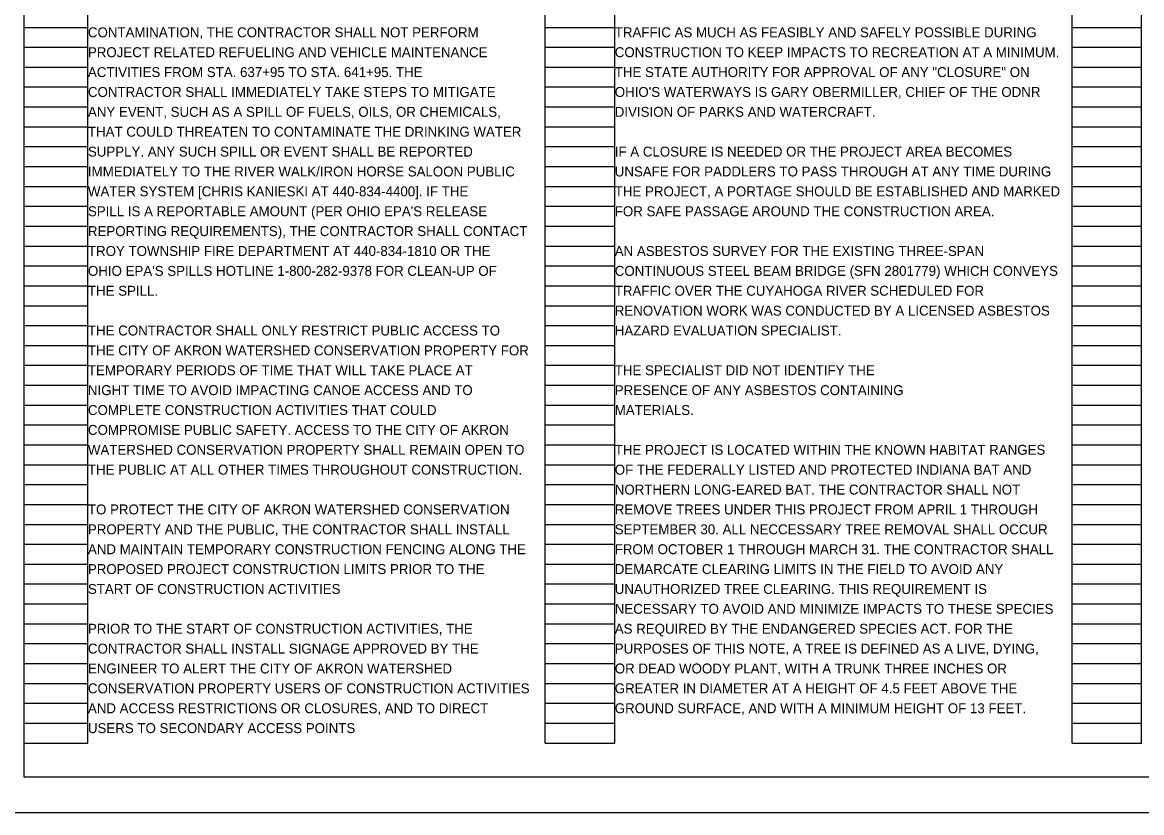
# Model space of a CAD drawing. Extents: x -6.4 to 41.8, y 0 to 22.
# Drawn here: x 1.98 to 17.74, y 0 to 11.13 of the extents above; entities that cross this region are included whole.
import ezdxf

# ---------------------------------------------------------------- set-up
doc = ezdxf.new("R2010")
doc.units = 0
for name, color, linetype in [('SC_Scratch1', 7, 'Continuous'), ('SH_Border', 7, 'Continuous'), ('SH_Cut_Line', 7, 'Continuous'), ('SH_Text', 7, 'Continuous')]:
    doc.layers.add(name, color=color, linetype=linetype)

msp = doc.modelspace()

# ---------------------------------------------------------------- linework, layer by layer
at = {"layer": 'SC_Scratch1'}
for p, q in [((2, 0.98), (2, 21.14)), ((2.9, 0.98), (2.9, 21.14)), ((9.34, 0.98), (9.34, 21.14)), ((10.32, 0.98), (10.32, 21.14)), ((16.76, 0.98), (16.76, 21.14)), ((17.74, 0.98), (17.74, 21.14)), ((2, 11.06), (2.9, 11.06)), ((9.34, 11.06), (10.32, 11.06)), ((16.76, 11.06), (17.74, 11.06)), ((2, 10.78), (2.9, 10.78)), ((9.34, 10.78), (10.32, 10.78)), ((16.76, 10.78), (17.74, 10.78)), ((2, 10.5), (2.9, 10.5)), ((9.34, 10.5), (10.32, 10.5)), ((16.76, 10.5), (17.74, 10.5)), ((2, 10.22), (2.9, 10.22)), ((9.34, 10.22), (10.32, 10.22)), ((16.76, 10.22), (17.74, 10.22)), ((2, 9.94), (2.9, 9.94)), ((9.34, 9.94), (10.32, 9.94)), ((16.76, 9.94), (17.74, 9.94)), ((2, 9.66), (2.9, 9.66)), ((9.34, 9.66), (10.32, 9.66)), ((16.76, 9.66), (17.74, 9.66)), ((2, 9.38), (2.9, 9.38)), ((9.34, 9.38), (10.32, 9.38)), ((16.76, 9.38), (17.74, 9.38)), ((2, 9.1), (2.9, 9.1)), ((9.34, 9.1), (10.32, 9.1)), ((16.76, 9.1), (17.74, 9.1)), ((2, 8.82), (2.9, 8.82)), ((9.34, 8.82), (10.32, 8.82)), ((16.76, 8.82), (17.74, 8.82)), ((2, 8.54), (2.9, 8.54)), ((9.34, 8.54), (10.32, 8.54)), ((16.76, 8.54), (17.74, 8.54)), ((2, 8.26), (2.9, 8.26)), ((9.34, 8.26), (10.32, 8.26)), ((16.76, 8.26), (17.74, 8.26)), ((2, 7.98), (2.9, 7.98)), ((9.34, 7.98), (10.32, 7.98)), ((16.76, 7.98), (17.74, 7.98)), ((2, 7.7), (2.9, 7.7)), ((9.34, 7.7), (10.32, 7.7)), ((16.76, 7.7), (17.74, 7.7)), ((2, 7.42), (2.9, 7.42)), ((9.34, 7.42), (10.32, 7.42)), ((16.76, 7.42), (17.74, 7.42)), ((2, 7.14), (2.9, 7.14)), ((9.34, 7.14), (10.32, 7.14)), ((16.76, 7.14), (17.74, 7.14)), ((2, 6.86), (2.9, 6.86)), ((9.34, 6.86), (10.32, 6.86)), ((16.76, 6.86), (17.74, 6.86)), ((2, 6.58), (2.9, 6.58)), ((9.34, 6.58), (10.32, 6.58)), ((16.76, 6.58), (17.74, 6.58)), ((2, 6.3), (2.9, 6.3)), ((9.34, 6.3), (10.32, 6.3)), ((16.76, 6.3), (17.74, 6.3)), ((2, 6.02), (2.9, 6.02)), ((9.34, 6.02), (10.32, 6.02)), ((16.76, 6.02), (17.74, 6.02)), ((2, 5.74), (2.9, 5.74)), ((9.34, 5.74), (10.32, 5.74)), ((16.76, 5.74), (17.74, 5.74)), ((2, 5.46), (2.9, 5.46)), ((9.34, 5.46), (10.32, 5.46)), ((16.76, 5.46), (17.74, 5.46)), ((2, 5.18), (2.9, 5.18)), ((9.34, 5.18), (10.32, 5.18)), ((16.76, 5.18), (17.74, 5.18)), ((2, 4.9), (2.9, 4.9)), ((9.34, 4.9), (10.32, 4.9)), ((16.76, 4.9), (17.74, 4.9)), ((2, 4.62), (2.9, 4.62)), ((9.34, 4.62), (10.32, 4.62)), ((16.76, 4.62), (17.74, 4.62)), ((2, 4.34), (2.9, 4.34)), ((9.34, 4.34), (10.32, 4.34)), ((16.76, 4.34), (17.74, 4.34)), ((2, 4.06), (2.9, 4.06)), ((9.34, 4.06), (10.32, 4.06)), ((16.76, 4.06), (17.74, 4.06)), ((2, 3.78), (2.9, 3.78)), ((9.34, 3.78), (10.32, 3.78)), ((16.76, 3.78), (17.74, 3.78)), ((2, 3.5), (2.9, 3.5)), ((9.34, 3.5), (10.32, 3.5)), ((16.76, 3.5), (17.74, 3.5)), ((2, 3.22), (2.9, 3.22)), ((9.34, 3.22), (10.32, 3.22)), ((16.76, 3.22), (17.74, 3.22)), ((2, 2.94), (2.9, 2.94)), ((9.34, 2.94), (10.32, 2.94)), ((16.76, 2.94), (17.74, 2.94)), ((2, 2.66), (2.9, 2.66)), ((9.34, 2.66), (10.32, 2.66)), ((16.76, 2.66), (17.74, 2.66)), ((2, 2.38), (2.9, 2.38)), ((9.34, 2.38), (10.32, 2.38)), ((16.76, 2.38), (17.74, 2.38)), ((2, 2.1), (2.9, 2.1)), ((9.34, 2.1), (10.32, 2.1)), ((16.76, 2.1), (17.74, 2.1)), ((2, 1.82), (2.9, 1.82)), ((9.34, 1.82), (10.32, 1.82)), ((16.76, 1.82), (17.74, 1.82)), ((2, 1.54), (2.9, 1.54)), ((9.34, 1.54), (10.32, 1.54)), ((16.76, 1.54), (17.74, 1.54)), ((2, 1.26), (2.9, 1.26)), ((9.34, 1.26), (10.32, 1.26)), ((16.76, 1.26), (17.74, 1.26)), ((2, 0.98), (2.9, 0.98)), ((9.34, 0.98), (10.32, 0.98)), ((16.76, 0.98), (17.74, 0.98))]:
    msp.add_line(p, q, dxfattribs=at)
at = {"layer": 'SH_Border'}
msp.add_lwpolyline([(2, 21.5), (33.5, 21.5), (33.5, 0.5), (2, 0.5)], close=True, dxfattribs=at)
at = {"layer": 'SH_Cut_Line'}
msp.add_lwpolyline([(0, 0), (34, 0), (34, 22), (0, 22)], close=True, dxfattribs=at)

# ---------------------------------------------------------------- texts
at = {"layer": 'SH_Text'}
for s, p in [('CONTAMINATION, THE CONTRACTOR SHALL NOT PERFORM ', (2.9, 10.92)), ('TRAFFIC AS MUCH AS FEASIBLY AND SAFELY POSSIBLE DURING ', (10.32, 10.92)), ('PROJECT RELATED REFUELING AND VEHICLE MAINTENANCE ', (2.9, 10.64)), ('CONSTRUCTION TO KEEP IMPACTS TO RECREATION AT A MINIMUM. ', (10.32, 10.64)), ('ACTIVITIES FROM STA. 637+95 TO STA. 641+95. THE ', (2.9, 10.36)), ('THE STATE AUTHORITY FOR APPROVAL OF ANY "CLOSURE" ON ', (10.32, 10.36)), ('CONTRACTOR SHALL IMMEDIATELY TAKE STEPS TO MITIGATE ', (2.9, 10.08)), ("OHIO'S WATERWAYS IS GARY OBERMILLER, CHIEF OF THE ODNR ", (10.32, 10.08)), ('ANY EVENT, SUCH AS A SPILL OF FUELS, OILS, OR CHEMICALS, ', (2.9, 9.8)), ('DIVISION OF PARKS AND WATERCRAFT. ', (10.32, 9.8)), ('THAT COULD THREATEN TO CONTAMINATE THE DRINKING WATER ', (2.9, 9.52)), ('SUPPLY. ANY SUCH SPILL OR EVENT SHALL BE REPORTED ', (2.9, 9.24)), ('IF A CLOSURE IS NEEDED OR THE PROJECT AREA BECOMES ', (10.32, 9.24)), ('IMMEDIATELY TO THE RIVER WALK/IRON HORSE SALOON PUBLIC ', (2.9, 8.96)), ('UNSAFE FOR PADDLERS TO PASS THROUGH AT ANY TIME DURING ', (10.32, 8.96)), ('WATER SYSTEM [CHRIS KANIESKI AT 440-834-4400]. IF THE ', (2.9, 8.68)), ('THE PROJECT, A PORTAGE SHOULD BE ESTABLISHED AND MARKED ', (10.32, 8.68)), ("SPILL IS A REPORTABLE AMOUNT (PER OHIO EPA'S RELEASE ", (2.9, 8.4)), ('FOR SAFE PASSAGE AROUND THE CONSTRUCTION AREA. ', (10.32, 8.4)), ('REPORTING REQUIREMENTS), THE CONTRACTOR SHALL CONTACT ', (2.9, 8.12)), ('TROY TOWNSHIP FIRE DEPARTMENT AT 440-834-1810 OR THE ', (2.9, 7.84)), ('AN ASBESTOS SURVEY FOR THE EXISTING THREE-SPAN ', (10.32, 7.84)), ("OHIO EPA'S SPILLS HOTLINE 1-800-282-9378 FOR CLEAN-UP OF ", (2.9, 7.56)), ('CONTINUOUS STEEL BEAM BRIDGE (SFN 2801779) WHICH CONVEYS ', (10.32, 7.56)), ('THE SPILL. ', (2.9, 7.28)), ('TRAFFIC OVER THE CUYAHOGA RIVER SCHEDULED FOR ', (10.32, 7.28)), ('RENOVATION WORK WAS CONDUCTED BY A LICENSED ASBESTOS ', (10.32, 7)), ('THE CONTRACTOR SHALL ONLY RESTRICT PUBLIC ACCESS TO ', (2.9, 6.72)), ('HAZARD EVALUATION SPECIALIST.', (10.32, 6.72)), ('THE CITY OF AKRON WATERSHED CONSERVATION PROPERTY FOR ', (2.9, 6.44)), ('TEMPORARY PERIODS OF TIME THAT WILL TAKE PLACE AT ', (2.9, 6.16)), ('THE SPECIALIST DID NOT IDENTIFY THE ', (10.32, 6.16)), ('NIGHT TIME TO AVOID IMPACTING CANOE ACCESS AND TO ', (2.9, 5.88)), ('PRESENCE OF ANY ASBESTOS CONTAINING', (10.32, 5.88)), ('COMPLETE CONSTRUCTION ACTIVITIES THAT COULD ', (2.9, 5.6)), ('MATERIALS.', (10.32, 5.6)), ('COMPROMISE PUBLIC SAFETY. ACCESS TO THE CITY OF AKRON ', (2.9, 5.32)), ('WATERSHED CONSERVATION PROPERTY SHALL REMAIN OPEN TO ', (2.9, 5.04)), ('THE PROJECT IS LOCATED WITHIN THE KNOWN HABITAT RANGES ', (10.32, 5.04)), ('THE PUBLIC AT ALL OTHER TIMES THROUGHOUT CONSTRUCTION. ', (2.9, 4.76)), ('OF THE FEDERALLY LISTED AND PROTECTED INDIANA BAT AND ', (10.32, 4.76)), ('NORTHERN LONG-EARED BAT. THE CONTRACTOR SHALL NOT ', (10.32, 4.48)), ('TO PROTECT THE CITY OF AKRON WATERSHED CONSERVATION ', (2.9, 4.2)), ('REMOVE TREES UNDER THIS PROJECT FROM APRIL 1 THROUGH ', (10.32, 4.2)), ('PROPERTY AND THE PUBLIC, THE CONTRACTOR SHALL INSTALL ', (2.9, 3.92)), ('SEPTEMBER 30. ALL NECCESSARY TREE REMOVAL SHALL OCCUR ', (10.32, 3.92)), ('AND MAINTAIN TEMPORARY CONSTRUCTION FENCING ALONG THE ', (2.9, 3.64)), ('FROM OCTOBER 1 THROUGH MARCH 31. THE CONTRACTOR SHALL ', (10.32, 3.64)), ('PROPOSED PROJECT CONSTRUCTION LIMITS PRIOR TO THE ', (2.9, 3.36)), ('DEMARCATE CLEARING LIMITS IN THE FIELD TO AVOID ANY ', (10.32, 3.36)), ('START OF CONSTRUCTION ACTIVITIES', (2.9, 3.08)), ('UNAUTHORIZED TREE CLEARING. THIS REQUIREMENT IS ', (10.32, 3.08)), ('NECESSARY TO AVOID AND MINIMIZE IMPACTS TO THESE SPECIES ', (10.32, 2.8)), ('PRIOR TO THE START OF CONSTRUCTION ACTIVITIES, THE ', (2.9, 2.52)), ('AS REQUIRED BY THE ENDANGERED SPECIES ACT. FOR THE ', (10.32, 2.52)), ('CONTRACTOR SHALL INSTALL SIGNAGE APPROVED BY THE ', (2.9, 2.24)), ('PURPOSES OF THIS NOTE, A TREE IS DEFINED AS A LIVE, DYING, ', (10.32, 2.24)), ('ENGINEER TO ALERT THE CITY OF AKRON WATERSHED ', (2.9, 1.96)), ('OR DEAD WOODY PLANT, WITH A TRUNK THREE INCHES OR ', (10.32, 1.96)), ('CONSERVATION PROPERTY USERS OF CONSTRUCTION ACTIVITIES ', (2.9, 1.68)), ('GREATER IN DIAMETER AT A HEIGHT OF 4.5 FEET ABOVE THE ', (10.32, 1.68)), ('AND ACCESS RESTRICTIONS OR CLOSURES, AND TO DIRECT ', (2.9, 1.4)), ('GROUND SURFACE, AND WITH A MINIMUM HEIGHT OF 13 FEET. ', (10.32, 1.4)), ('USERS TO SECONDARY ACCESS POINTS', (2.9, 1.12))]:
    msp.add_text(s, height=0.14, dxfattribs=at).set_placement(p)

doc.saveas('drawing.dxf')
